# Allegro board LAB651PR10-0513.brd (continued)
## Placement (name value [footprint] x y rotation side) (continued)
J13  -  [JUMP_43X118]  91.79 68.38 180 top
J14  -  [JUMP_43X118]  91.79 61.4 180 top
J15  -  [JUMP_43X118]  133.62 6.15 0 top
J16  -  [JUMP_43X118]  99.41 30.03 180 top
J519  -  [JUMP_43X39]  10.39 66.98 0 top
JDIMM1  -  [BELLW_80001-1021_204P]  96.15 47.7 180 bottom
JEDP  STARC_107K40-000001-G2  [STARC_107K40-000001-G2_40P]  1.76 99 270 bottom
JFAN  ACES_88231-03041  [ACES_88231-03041_3P]  7.05 72.04 180 bottom
JHDD  E&T_4260K-F10N-00L  [E-T_4260K-F10N-00L_10P]  180.71 12.52 180 bottom
JHDMI  CONCR_099ATAC19NBLCNF  [CONCR_099ATAC19NBLCNF_19P]  203.55 89.7 270 bottom
JHDT1  SAMTE_ASP-136446-07-B  [SAMTE_ASP-136446-07-B_20P-T]  92.36 91.1 270 top
JHP  SINGA_2SJ3080-001111F  [SINGA_2SJ3080-001111F_6P]  201.74 36.91 90 bottom
JIO  ACES_51524-0160N-001  [ACES_51524-0160N-001_16P]  25.55 43.95 90 bottom
JKB  HB_A823020-SBHR21  [HB_A823020-SBHR21_30P]  91.75 47.75 270 top
JKBBL  ACES_50524-00401-P01  [ACES_50524-00401-P01_4P-T]  120.35 16.82 270 top
JLAN  J-L_TNBNRAC80015008  [J-L_TNBNRAC80015008_8P]  201.1 109.12 270 bottom
JLED  ACES_51524-0080N-001  [ACES_51524-0080N-001_8P]  12.75 58.3 270 top
JNGFF  LOTES_APCI0019-P009A  [LOTES_APCI0019-P009A_67P]  172.48 57.83 0 bottom
JP3  2MM  [JUMP_43X39]  166.05 115.8 90 bottom
JP13  -  [JUMP_43X79]  188.4 12.16 270 top
JRTC  ACES_50271-0020N-001  [ACES_50271-0020N-001_2P]  28.21 11.33 270 bottom
JSPK  ACES_50278-00401-001  [ACES_50278-00401-001_4P]  208.6 14.05 180 bottom
JTP  ACES_51524-0080N-001  [ACES_51524-0080N-001_8P]  20.65 60.25 0 top
JUSB1  TAITW_PUBAU6-09FLBS1NN4H0  [TAITW_PUBAU6-09FLBS1NN4H0_9P]  199.29 61.75 270 bottom
JUSB2  TAITW_PUBAU6-09FLBS1NN4H0  [TAITW_PUBAU6-09FLBS1NN4H0_9P]  199.29 43.55 270 bottom
LA1  BLM15BB221SN1D_2P  [MURAT_BLM15BB221SN1D_2P]  199.07 14.53 270 bottom
LA3  BLM15BB121SN1D_0402  [R_0402]  210.45 16.92 90 top
LA4  BLM15BB121SN1D_0402  [R_0402]  208.21 16.91 90 top
LA5  BLM15BB121SN1D_0402  [R_0402]  205.61 16.9 90 top
LA6  BLM15BB121SN1D_0402  [R_0402]  203.43 16.9 90 top
LA7  BLM15PX330SN1D 0402  [MURAT_BLM15BD601SN1D_2P]  191.57 33.2 180 bottom
LA8  CHILISIN NBQ100505T-800Y-N_0402  [MURAT_BLM15BD601SN1D_2P]  191.48 29.07 180 bottom
LA9  CHILISIN NBQ100505T-800Y-N_0402  [MURAT_BLM15BD601SN1D_2P]  191.48 27.49 180 bottom
LA10  BLM15PX330SN1D 0402  [MURAT_BLM15BD601SN1D_2P]  191.57 31.42 180 bottom
LE1  FBMA-L11-160808-800LMT_0603  [KC_FBMA-L11-160808-800LMT_2P]  108.13 35.48 270 bottom
LE2  FBMA-L11-160808-800LMT_0603  [KC_FBMA-L11-160808-800LMT_2P]  109.66 35.48 270 bottom
LH1  HCB1608KF-221T20_0603  [CHENG_MBK1608221YZF_2P]  167.99 8.82 180 top
LH5  FBMA-L11-201209-221LMA30T_0805  [R_0805]  151.57 4.41 90 top
LH6  HCB1608KF-221T20_0603  [CHENG_MBK1608221YZF_2P]  159.95 6.62 90 top
LH7  HCB1608KF-221T20_0603  [CHENG_MBK1608221YZF_2P]  166.39 10.09 0 top
LH9  HCB1608KF-221T20_0603  [CHENG_MBK1608221YZF_2P]  153.77 2.49 90 top
LH10  HCB1608KF-221T20_0603  [CHENG_MBK1608221YZF_2P]  149.83 6.02 180 top
LH11  HCB1608KF-221T20_0603  [CHENG_MBK1608221YZF_2P]  155.11 2.49 90 top
LH12  HCB1608KF-221T20_0603  [CHENG_MBK1608221YZF_2P]  166.93 4.08 270 top
LH13  HCB1608KF-221T20_0603  [CHENG_MBK1608221YZF_2P]  171.78 30.47 180 top
LH14  HCB1608KF-221T20_0603  [CHENG_MBK1608221YZF_2P]  171.78 29.14 180 top
LH15  FBMA-L11-201209-221LMA30T_0805  [R_0805]  156.65 4.08 270 top
LI1  DLW21HN670HQ2L_4P  [MURAT_DLW21SN670HQ2L_4P]  196.93 68.6 270 bottom
LI2  MURATA DLW21SN900HQ2L  [KC_WCM-2012HS-900T_4P]  195.02 59.53 90 bottom
LI3  DLW21HN670HQ2L_4P  [MURAT_DLW21SN670HQ2L_4P]  195.15 68.6 270 bottom
LI4  DLW21HN670HQ2L_4P  [MURAT_DLW21SN670HQ2L_4P]  188.31 48.08 0 bottom
LI5  MURATA DLW21SN900HQ2L  [KC_WCM-2012HS-900T_4P]  188.31 43.22 0 bottom
LI6  DLW21HN670HQ2L_4P  [MURAT_DLW21SN670HQ2L_4P]  188.31 46.3 0 bottom
LI7  MURATA DLW21SN900HQ2L  [KC_WCM-2012HS-900T_4P]  30.75 57.86 180 bottom
LI8  MURATA DLW21SN900HQ2L  [KC_WCM-2012HS-900T_4P]  30.75 54.87 180 bottom
LL1  2.2UH_LQM2MPN2R2NG0L_30%  [MURAT_LQM2MPN2R2NG0L_2P]  167.35 109.4 180 bottom
LV2  BLM15BD121SN1D_0402  [R_0402]  80.14 84.76 180 bottom
LV3  BLM15BD121SN1D_0402  [R_0402]  74.81 76.13 180 top
LV4  BLM15BD121SN1D_0402  [R_0402]  68.64 86.42 270 top
LV6  BLM15BB221SN1D_2P  [MURAT_BLM15BB221SN1D_2P]  60.13 99.74 270 top
LV7  BLM15BD121SN1D_0402  [R_0402]  55.81 93.27 0 top
LV8  BLM15BD121SN1D_0402  [R_0402]  57.84 96.02 270 top
LV25  BLM15BD121SN1D_0402  [R_0402]  60.64 82.17 0 top
LV26  BLM15BD121SN1D_0402  [R_0402]  60.64 81.31 0 top
LX1  FBMA-L11-201209-221LMA30T_0805  [KC_FBMA-L11-201209-221LMA30_2P]  12.38 84.96 90 top
LX2  MURATA DLW21HN900HQ2L  [KC_WCM-2012HS-900T_4P]  196.69 82.33 0 bottom
LX3  MURATA DLW21HN900HQ2L  [KC_WCM-2012HS-900T_4P]  196.69 78.78 0 bottom
LX4  MURATA DLW21HN900HQ2L  [KC_WCM-2012HS-900T_4P]  196.69 85.89 0 bottom
LX5  MURATA DLW21HN900HQ2L  [KC_WCM-2012HS-900T_4P]  196.69 89.44 0 bottom
LX6  MURATA DLW21SN900HQ2L  [KC_WCM-2012HS-900T_4P]  5.64 85.46 180 top
NOREF  -  []  165.8 69.8 0 top
NOREF#2  -  []  115.1 82 0 top
NOREF#3  -  []  183 32.1 0 top
NOREF#4  -  []  181.73 91.35 0 top
NOREF#5  -  []  41.67 60.57 0 top
NOREF#6  -  []  102.67 41.83 0 top
NOREF#7  -  []  22.1 92.1 0 top
NOREF#8  -  []  195 4 0 top
NOREF#9  -  []  195.5 96.4 0 top
NOREF#10  -  []  21.8 9.8 0 top
NOREF#11  -  []  115.1 107.4 0 top
NOREF#12  -  []  72.29 -30.86 0 top
NOREF#13  -  []  82.8 57.8 0 top
NOREF#14  -  []  105.85 50.6 0 top
NOREF#15  -  []  27.8 118.8 0 top
NOREF#16  -  []  68.32 163 0 top
NOREF#17  -  []  117.6 65.21 0 top
NOREF#18  -  []  160.1 107.4 0 top
NOREF#19  -  []  86.32 106.83 0 top
NOREF#20  -  []  101 3.5 0 top
NOREF#21  -  []  166.72 76.62 0 top
NOREF#22  -  []  160.1 82 0 top
NOREF#23  -  []  137.6 44.95 0 top
NOREF#24  -  []  102.42 76.45 180 bottom
NOREF#25  -  []  106.74 79.58 180 bottom
NOREF#26  -  []  113.66 95.08 180 bottom
NOREF#27  -  []  151.6 64.55 180 bottom
PBATT  LLTOP_ALLTOP C144LS-109A9-L 9P BATT P2  [ALLTO_C144LS-109A9-L_9P-T]  13.95 12.52 90 bottom
PC1  1000P_0402_50V7K  [C_0402]  16.44 116.84 270 bottom
PC2  100P_0402_50V8J  [C_0402]  17.33 116.84 270 bottom
PC3  1000P_0402_50V7K  [C_0402]  17.33 113.77 90 bottom
PC4  100P_0402_50V8J  [C_0402]  16.31 113.77 90 bottom
PC5  0.1U_0402_25V6  [C_0402]  36.56 108.13 0 top
PC7  0.01U_0402_25V7K  [C_0402]  24.95 28.17 90 top
PC8  1000P_0402_50V7K  [C_0402]  19.23 30.46 90 top
PC9  10P_0402_25V8J  [C_0402]  25.84 28.17 90 top
PC13  0.1U_0402_16V7K  [C_0402]  127.08 28.25 180 bottom
PC16  0.1U_0402_16V7K  [C_0402]  36.51 113.67 270 top
PC100  4.7U_0603_6.3V6K  [C_0603]  75.22 9.29 180 top
PC101  220U_6.3V_M  [C_MP6VLPS220MC4R2]  70.65 27.86 90 bottom
PC102  100P_0402_50V8J  [C_0402]  76.35 20.11 180 top
PC103  680P_0402_50V7K  [C_0402]  70.34 22.99 270 top
PC104  0.22U_0603_25V7K  [C_0603]  73.21 21.45 90 top
PC105  1U_0603_25V6K  [C_0603]  70.33 18.83 270 bottom
PC106  4.7U_0603_10V6K  [C_0603]  68.23 17.86 270 bottom
PC107  220U_6.3V_M  [C_MP6VLPS220MC4R2]  71 8.36 270 bottom
PC108  100P_0402_50V8J  [C_0402]  75.42 16.82 0 bottom
PC109  4.7U_0603_10V6K  [C_0603]  75.49 18.1 0 top
PC110  0.22U_0603_25V7K  [C_0603]  71.77 12.98 90 top
PC111  680P_0402_50V7K  [C_0402]  67.43 14.01 90 top
PC112  10U_0805_25V6K  [C_0805]  62.81 19.49 0 bottom
PC113  0.1U_0402_25V6  [C_0402]  62.85 18.44 0 top
PC114  2200P_0402_50V7K  [C_0402]  62.85 19.33 0 top
PC115  10U_0805_25V6K  [C_0805]  62.32 20.63 0 top
PC118  10P_0402_25V8J  [C_0402]  62.87 18.17 0 bottom
PC119  10P_0402_25V8J  [C_0402]  62.87 17.28 0 bottom
PC200  0.1U_0603_25V7K  [C_0603]  88.89 13.01 180 bottom
PC201  2200P_0402_50V7K  [C_0402]  83.11 16.49 90 bottom
PC202  0.1U_0402_10V7K  [C_0402]  81.03 10.6 180 bottom
PC203  0.1U_0402_10V7K  [C_0402]  81.03 8.82 180 bottom
PC204  1U_0603_10V6K  [C_0603]  84.13 15.99 270 top
PC205  10U_0805_6.3V6K  [C_0805]  88.7 9.42 270 bottom
PC206  10U_0805_25V6K  [C_0805]  86.29 16.22 90 bottom
PC207  680P_0402_50V7K  [C_0402]  89.29 21.77 180 bottom
PC208  0.1U_0402_25V6  [C_0402]  82.23 16.49 90 bottom
PC209  1U_0603_10V6K  [C_0603]  82.86 14.6 90 top
PC210  0.033U_0402_16V7K  [C_0402]  84.13 8.26 270 bottom
PC211  10U_0805_6.3V6K  [C_0805]  87.27 7.93 180 bottom
PC212  10U_0805_25V6K  [C_0805]  84.51 16.22 90 bottom
PC213  330U_2.5V_M  [C_MP6VU330MC6]  99.37 10.98 180 bottom
PC214  220P_0402_25V8J  [C_0402]  81.9 7.8 0 top
PC215  10P_0402_25V8J  [C_0402]  81.34 16.49 90 bottom
PC300  330U_D2_2V_Y  [C_D2]  172.52 41.25 90 bottom
PC301  0.1U_0402_25V6  [C_0402]  176.97 49.13 90 top
PC302  2200P_0402_50V7K  [C_0402]  176.08 49.13 90 top
PC303  10U_0805_25V6K  [C_0805]  178.02 48.57 0 top
PC304  10U_0805_25V6K  [C_0805]  178.02 46.79 0 top
PC305  0.1U_0603_25V7K  [C_0603]  177.92 48.82 0 bottom
PC306  0.1U_0402_16V7K  [C_0402]  179.89 54.74 270 top
PC307  1U_0603_6.3V6M  [C_0603]  180.46 49.46 0 bottom
PC309  680P_0402_50V7K  [C_0402]  184.54 46.73 180 top
PC310  22U_0603_6.3V6M  [C_0603]  206.74 6.76 0 top
PC311  68P_0402_50V8J  [C_0402]  210.48 10.98 180 top
PC312  22U_0603_6.3V6M  [C_0603]  203.23 10.67 0 top
PC313  22U_0603_6.3V6M  [C_0603]  203.23 11.98 0 top
PC314  0.1U_0402_16V7K  [C_0402]  205.64 11.28 90 top
PC315  680P_0402_50V7K  [C_0402]  206.74 4.74 90 top
PC316  10P_0402_25V8J  [C_0402]  174.11 45.34 270 top
PC400  22U_0603_6.3V6M  [C_0603]  110.48 7.93 0 bottom
PC401  22U_0603_6.3V6M  [C_0603]  110.48 9.2 0 bottom
PC402  68P_0402_50V8J  [C_0402]  110.42 2.26 90 bottom
PC403  22U_0603_6.3V6M  [C_0603]  121.09 4.18 270 bottom
PC404  1U_0402_10V6K  [C_0402]  109.15 5.31 90 bottom
PC405  22U_0603_6.3V6M  [C_0603]  121.09 5.58 90 bottom
PC406  22U_0603_6.3V6M  [C_0603]  122.36 5.58 90 bottom
PC407  22U_0603_6.3V6M  [C_0603]  122.36 4.18 270 bottom
PC408  0.1U_0402_16V7K  [C_0402]  113.21 3.18 270 bottom
PC409  680P_0402_50V7K  [C_0402]  113.98 9.78 270 bottom
PC410  0.1U_0402_16V7K  [C_0402]  110.4 4.28 180 bottom
PC411  22U_0603_6.3V6M  [C_0603]  86.57 25.25 180 bottom
PC412  68P_0402_50V8J  [C_0402]  82.9 29.52 0 bottom
PC413  22U_0603_6.3V6M  [C_0603]  92.45 28 0 bottom
PC414  22U_0603_6.3V6M  [C_0603]  90.8 28 180 bottom
PC415  0.1U_0402_16V7K  [C_0402]  87.74 29.82 90 bottom
PC416  680P_0402_50V7K  [C_0402]  86.59 23.03 90 bottom
PC500  0.01U_0402_50V7K  [C_0402]  64.12 119.31 0 top
PC501  680P_0402_50V7K  [C_0402]  58.78 120.2 0 top
PC502  0.1U_0603_25V7K  [C_0603]  61.02 117.83 270 bottom
PC503  10U_0805_25V6K  [C_0805]  72.5 105.94 0 top
PC504  10U_0805_25V6K  [C_0805]  72.79 103.43 0 top
PC505  10U_0805_25V6K  [C_0805]  72.36 103.43 0 bottom
PC506  330P_0402_50V  [C_0402]  58.78 119.31 0 top
PC507  0.22U_0603_25V7K  [C_0603]  70.35 111.43 180 top
PC508  0.1U_0402_16V7K  [C_0402]  64.75 107.4 0 bottom
PC509  470P_0402_50V8J  [C_0402]  63.25 118.42 180 top
PC510  68P_0402_50V8J  [C_0402]  61.47 118.42 180 top
PC511  680P_0603_50V7K  [C_0603]  79.62 110.93 180 bottom
PC512  0.1U_0402_25V6  [C_0402]  64.83 108.44 90 bottom
PC513  1U_0402_6.3V6K  [C_0402]  60.84 113.72 180 bottom
PC514  2.2U_0603_10V7K  [C_0603]  60.64 107.5 270 top
PC515  2.2U_0603_10V7K  [C_0603]  68.95 116.51 0 top
PC518  100U_25V_M  [C_ECST250ADA101MF611]  72.62 114.07 270 bottom
PC519  10U_0805_25V6K  [C_0805]  78.8 116.43 90 bottom
PC520  10U_0805_25V6K  [C_0805]  81.5 113.85 0 bottom
PC521  10U_0805_25V6K  [C_0805]  81.5 113.85 0 top
PC522  0.1U_0402_25V6  [C_0402]  81.9 112.45 0 bottom
PC523  2200P_0402_50V7K  [C_0402]  81.9 112.45 0 top
PC524  0.22U_0603_25V7K  [C_0603]  70.35 115.24 180 top
PC525  0.1U_0402_16V7K  [C_0402]  66.81 118.42 180 top
PC526  0.1U_0402_25V6  [C_0402]  56.19 116.44 90 top
PC527  0.1U_0402_25V6  [C_0402]  57.08 115.57 270 top
PC528  680P_0603_50V7K  [C_0603]  87.75 113.72 180 top
PC529  68P_0402_50V8J  [C_0402]  63.51 107.5 180 top
PC530  470P_0402_50V8J  [C_0402]  65.28 107.5 180 top
PC531  330P_0402_50V  [C_0402]  67.06 107.5 180 top
PC532  0.1U_0402_25V6  [C_0402]  67.67 120.2 0 top
PC533  680P_0402_50V7K  [C_0402]  67.06 105.72 180 top
PC534  0.01U_0402_50V7K  [C_0402]  68.81 106.61 0 top
PC535  0.1U_0402_25V6  [C_0402]  65.72 110.21 90 bottom
PC700  0.1U_0603_25V7K  [C_0603]  31.22 33.83 270 top
PC701  5600P_0402_25V7K  [C_0402]  29.74 30.83 270 top
PC702  4.7U_0805_25V6-K  [C_0805]  37.01 31.12 270 top
PC703  4.7U_0805_25V6-K  [C_0805]  38.77 31.12 270 top
PC704  2200P_0402_25V7K  [C_0402]  34.45 30.61 270 top
PC705  0.1U_0603_25V7K  [C_0603]  35.52 30.99 270 top
PC706  0.1U_0603_25V7K  [C_0603]  47.4 17.4 270 top
PC707  0.1U_0603_25V7K  [C_0603]  46.16 17.4 270 top
PC708  0.1U_0402_10V7K  [C_0402]  25.21 37.87 90 top
PC709  0.047U_0603_25V7M  [C_0603]  47.49 18.98 180 bottom
PC710  1U_0603_10V6K  [C_0603]  44.94 17.4 270 top
PC711  1U_0603_25V6K  [C_0603]  41.18 16.54 0 top
PC712  0.01U_0402_50V7K  [C_0402]  46.35 15.06 0 top
PC713  0.1U_0603_25V7K  [C_0603]  42.68 20.6 270 bottom
PC714  1U_0603_10V6K  [C_0603]  41.18 15.27 0 top
PC715  0.1U_0402_10V7K  [C_0402]  43.95 11.91 90 top
PC716  680P_0402_50V7K  [C_0402]  44.65 30.5 180 bottom
PC717  10U 25V K X5R 0805  [C_0805]  27.11 20.29 270 bottom
PC718  10U 25V K X5R 0805  [C_0805]  25.2 20.29 270 bottom
PC719  10U 25V K X5R 0805  [C_0805]  23.3 20.29 270 bottom
PC720  10U 25V K X5R 0805  [C_0805]  21.39 20.29 270 bottom
PC721  2200P_0402_25V7K  [C_0402]  47.26 13.3 180 top
PC722  0.22U_0603_25V7K  [C_0603]  38.29 15.24 270 top
PC723  0.1U_0402_10V7K  [C_0402]  48.62 11.31 0 bottom
PC725  0.1U_0402_16V7K  [C_0402]  46.97 9.94 270 bottom
PC726  0.1U_0603_25V7K  [C_0603]  38.28 12.78 270 top
PC727  0.01U_0402_25V7K  [C_0402]  50.39 12.21 270 bottom
PC728  1U_0603_25V6K  [C_0603]  30.77 38.11 0 top
PC836  330U_D3_2.5VY_R6M  [C_D3]  67.37 63.71 270 top
PC837  330U_D3_2.5VY_R6M  [C_D3]  67.14 68.13 180 top
PC838  330U_D2_2V_Y  [C_D2]  59.38 63.94 180 bottom
PC839  330U_D2_2V_Y  [C_D2]  63.47 63.95 0 bottom
PC840  2.2U_0402_6.3V6M  [C_0402]  64.98 87.05 270 top
PC841  2.2U_0402_6.3V6M  [C_0402]  61.45 88.35 0 top
PC842  2.2U_0402_6.3V6M  [C_0402]  64.4 89.26 180 top
PC843  2.2U_0402_6.3V6M  [C_0402]  62.74 66.86 180 bottom
PC844  2.2U_0402_6.3V6M  [C_0402]  65.79 67.75 180 bottom
PC845  2.2U_0402_6.3V6M  [C_0402]  65.79 69.52 180 bottom
PC846  2.2U_0402_6.3V6M  [C_0402]  62.74 69.52 180 bottom
PC847  2.2U_0402_6.3V6M  [C_0402]  67.75 67.03 90 bottom
PC848  2.2U_0402_6.3V6M  [C_0402]  66.86 67.03 90 bottom
PC849  2.2U_0402_6.3V6M  [C_0402]  62.74 68.64 180 bottom
PC850  2.2U_0402_6.3V6M  [C_0402]  65.79 68.64 180 bottom
PC851  2.2U_0402_6.3V6M  [C_0402]  67.38 83.21 90 top
PC852  2.2U_0402_6.3V6M  [C_0402]  63.55 82.26 90 top
PC853  10U_0603_6.3V6M  [C_0603]  68.81 66.9 90 bottom
PC854  10U_0603_6.3V6M  [C_0603]  54.46 64.33 180 top
PC855  10U_0603_6.3V6M  [C_0603]  69.16 59.67 90 bottom
PC856  10U_0603_6.3V6M  [C_0603]  70.08 66.9 90 bottom
PC857  10U_0603_6.3V6M  [C_0603]  54.45 65.56 180 top
PC858  10U_0603_6.3V6M  [C_0603]  69.16 58.53 270 bottom
PC859  0.1U_0402_10V7K  [C_0402]  62.74 67.75 180 bottom
PC860  0.1U_0402_10V7K  [C_0402]  65.79 66.86 180 bottom
PC869  2.2U_0402_6.3V6M  [C_0402]  62.74 70.41 180 bottom
PC871  2.2U_0402_6.3V6M  [C_0402]  66.73 88.29 180 top
PC872  2.2U_0402_6.3V6M  [C_0402]  66.86 89.26 90 top
PC901  22U_0603_6.3V6M  [C_0603]  135.58 94.45 270 top
PC902  22U_0603_6.3V6M  [C_0603]  136.85 96.87 270 top
PC903  22U_0603_6.3V6M  [C_0603]  135.58 96.87 270 top
PC904  22U_0603_6.3V6M  [C_0603]  136.85 99.28 270 top
PC905  22U_0603_6.3V6M  [C_0603]  135.58 99.28 270 top
PC906  22U_0603_6.3V6M  [C_0603]  136.85 101.69 270 top
PC907  22U_0603_6.3V6M  [C_0603]  135.58 101.69 270 top
PC908  22U_0603_6.3V6M  [C_0603]  140.02 94.45 270 top
PC909  22U_0603_6.3V6M  [C_0603]  141.29 94.45 270 top
PC910  22U_0603_6.3V6M  [C_0603]  136.85 94.45 270 top
PC911  22U_0603_6.3V6M  [C_0603]  138.75 94.45 270 top
PC912  22U_0603_6.3V6M  [C_0603]  140.02 96.87 270 top
PC913  22U_0603_6.3V6M  [C_0603]  138.75 96.87 270 top
PC914  0.22U_0402_10V6K  [C_0402]  137.1 91.14 90 top
PC915  0.22U_0402_10V6K  [C_0402]  137.99 91.14 90 top
PC916  0.01U_0402_25V7K  [C_0402]  135.32 91.14 90 top
PC917  0.01U_0402_25V7K  [C_0402]  136.21 91.14 90 top
PC918  0.01U_0402_25V7K  [C_0402]  139.77 91.14 90 top
PC919  180P_0402_50V8J  [C_0402]  141.54 91.14 90 top
PC920  180P_0402_50V8J  [C_0402]  140.65 91.16 90 top
PC921  180P_0402_50V8J  [C_0402]  138.88 91.14 90 top
PC922  330U_D2_2V_Y  [C_D2]  102.42 119.21 270 bottom
PC923  330U_D3_2.5VY_R6M  [C_D3]  131.73 114.79 180 top
PC924  330U_D3_2.5VY_R6M  [C_D3]  150.15 114.25 0 top
PC931  22U_0603_6.3V6M  [C_0603]  130.88 94.45 270 top
PC932  22U_0603_6.3V6M  [C_0603]  133.67 94.45 270 top
PC933  22U_0603_6.3V6M  [C_0603]  132.27 94.45 270 top
PC934  22U_0603_6.3V6M  [C_0603]  132.27 96.87 270 top
PC935  22U_0603_6.3V6M  [C_0603]  130.88 96.87 270 top
PC936  22U_0603_6.3V6M  [C_0603]  130.88 101.69 270 top
PC937  22U_0603_6.3V6M  [C_0603]  132.27 101.69 270 top
PC938  22U_0603_6.3V6M  [C_0603]  133.67 101.69 270 top
PC939  22U_0603_6.3V6M  [C_0603]  132.27 99.28 270 top
PC940  22U_0603_6.3V6M  [C_0603]  133.67 99.28 270 top
PC941  22U_0603_6.3V6M  [C_0603]  130.88 99.28 270 top
PC942  22U_0603_6.3V6M  [C_0603]  133.67 96.87 270 top
PC943  0.22U_0402_10V6K  [C_0402]  134.05 91.13 90 top
PC944  0.22U_0402_10V6K  [C_0402]  130.75 89.39 270 top
PC945  0.22U_0402_10V6K  [C_0402]  131.64 89.39 270 top
PC946  180P_0402_50V8J  [C_0402]  131.64 91.14 90 top
PC947  180P_0402_50V8J  [C_0402]  133.16 89.39 270 top
PC948  180P_0402_50V8J  [C_0402]  130.75 91.14 90 top
PC949  180P_0402_50V8J  [C_0402]  133.16 91.14 90 top
PC950  330U_D3_2.5VY_R6M  [C_D3]  111.79 114.91 0 top
PC951  330U_D3_2.5VY_R6M  [C_D3]  107.24 111.66 90 top
PC952  330U_D2_2V_Y  [C_D2]  107.54 110.21 270 bottom
PC1019  0.1U_0402_25V6K  [C_0402]  60.01 32.58 90 top
PC1020  1U_0603_10V6K  [C_0603]  61.21 39.17 180 top
PC1021  1U_0603_10V6K  [C_0603]  63.3 40.38 90 top
PC1022  1000P_0402_50V7K  [C_0402]  58.12 33.43 270 top
PC1023  10U_0805_25V6K  [C_0805]  57.84 45.22 90 top
PC1024  10U_0805_25V6K  [C_0805]  57.84 45.22 90 bottom
PC1025  2200P_0402_50V7K  [C_0402]  59.24 45.65 90 top
PC1026  0.22U_0603_25V7K  [C_0603]  59.49 43.17 270 bottom
PC1027  1000P_0402_50V7K  [C_0402]  57.16 39.55 180 top
PC1028  180P_0402_50V8J  [C_0402]  57.16 38.92 180 bottom
PC1029  680P_0603_50V7K  [C_0603]  56.24 46.22 90 bottom
PC1030  330P_0402_50V7K  [C_0402]  57.16 36.89 180 top
PC1031  0.01U_0402_50V7K  [C_0402]  57.16 35.87 180 bottom
PC1032  0.22U_0603_16V7K  [C_0603]  55.17 35.81 270 bottom
PC1033  390P_0402_50V7K  [C_0402]  54.08 39.43 0 bottom
PC1034  330P_0402_50V  [C_0402]  52.3 39.43 0 bottom
PC1035  0.1U_0603_50V7K  [C_0603]  56.38 35.12 0 top
PC1036  820P_0402_50V7K  [C_0402]  56.24 36.89 0 bottom
PC1040  0.01U_0402_50V7K  [C_0402]  58.02 38.66 0 top
PC1041  10U_0805_25V6K  [C_0805]  60.64 45.22 90 top
PC1042  0.1U_0402_25V6  [C_0402]  59.24 45.65 90 bottom
PC1043  0.22U_0603_25V7K  [C_0603]  63.56 43.3 270 bottom
PC1044  680P_0603_50V7K  [C_0603]  74.34 48.34 270 top
PC1045  2200P_0402_50V7K  [C_0402]  62.03 45.65 90 bottom
PC1046  10U_0805_25V6K  [C_0805]  63.43 45.25 90 bottom
PC1047  0.1U_0402_25V6K  [C_0402]  62.03 45.65 90 top
PC1048  10U_0805_25V6K  [C_0805]  63.43 45.25 90 top
PC1049  10U_0805_25V6K  [C_0805]  60.64 45.22 90 bottom
PC1050  0.22U_0402_10V6K  [C_0402]  56.24 33.68 0 bottom
PC1051  0.22U_0402_10V6K  [C_0402]  56.24 34.98 0 bottom
PC1052  10U 25V K X5R 0805  [C_0805]  65.33 45.25 90 bottom
PC1100  0.1U_0402_25V6  [C_0402]  40.37 41.2 0 top
PC1101  2200P_0402_50V7K  [C_0402]  40.37 40.06 0 top
PC1102  10U_0805_25V6K  [C_0805]  39.97 42.6 0 top
PC1103  0.1U_0603_25V7K  [C_0603]  35.49 44.7 90 bottom
PC1104  0.1U_0402_16V7K  [C_0402]  30.59 41.97 0 bottom
PC1105  1U_0603_10V6K  [C_0603]  35.49 47.24 90 bottom
PC1106  680P_0402_50V7K  [C_0402]  40.24 50.35 0 top
PC1108  330U_2.5V_M  [C_MP6VU330MC6]  43.62 52.63 180 bottom
PC1109  10P_0402_25V8J  [C_0402]  40.37 44.12 0 top
PC1300  22U_0603_6.3V6M  [C_0603]  74.54 65.59 0 bottom
PC1301  22U_0603_6.3V6M  [C_0603]  73.93 51.34 180 bottom
PC1302  0.1U_0402_10V7K  [C_0402]  74.1 52.38 180 top
PC1303  22U_0603_6.3V6M  [C_0603]  74.54 66.78 0 bottom
PC1304  680P_0402_50V7K  [C_0402]  76.38 54.92 180 top
PC1305  22U_0603_6.3V6M  [C_0603]  73.26 66.79 180 bottom
PC1306  22P_0402_50V8J  [C_0402]  77.27 53.27 270 top
PC1307  0.1U_0402_10V7K  [C_0402]  76.38 55.3 270 bottom
PC1308  22U_0603_6.3V6M  [C_0603]  73.26 65.57 180 bottom
PC1309  22U_0603_6.3V6M  [C_0603]  73.93 50.12 180 bottom
PD1  -  [TVNST52302AB0_SOT523-3]  17.77 18.72 90 top
PD2  -  [TVNST52302AB0_SOT523-3]  19.17 22.03 270 top
PD101  -  [TVNST52302AB0_SOT523-3]  74.43 12.92 180 top
PH1  100K_0402_1%_TSM0B104F4251RZ  [R_0402]  126.92 91.66 0 top
PH500  100K_0402_1%_TSM0B104F4251RZ  [R_0402]  98.02 102.42 0 bottom
PH501  100K_0402_1%_TSM0B104F4251RZ  [R_0402]  94.62 112.83 180 bottom
PH1002  470K_0402_5%_TSM0B474J4702RE  [R_0402]  50.56 44.56 270 top
PH1003  10K_0402_5%_ERTJ0ER103J  [R_0402]  50.88 57.52 90 bottom
PJP100  PAD-OPEN 4x4m  [JUMP_43X118]  75.5 20.77 0 bottom
PJP101  PAD-OPEN 4x4m  [JUMP_43X118]  76.09 13.77 0 bottom
PJP102  PAD-OPEN 4x4m  [JUMP_43X118]  75.5 26.04 0 bottom
PJP103  PAD-OPEN 4x4m  [JUMP_43X118]  76.09 8.56 0 bottom
PJP200  -  [JUMP_43X118]  101.4 24.91 90 bottom
PJP201  -  [JUMP_43X118]  96.2 24.91 90 bottom
PJP203  -  [JUMP_43X39]  90.68 7.98 90 bottom
PJP300  -  [JUMP_43X118]  171.55 44.51 180 top
PJP301  -  [JUMP_43X79]  211.22 7.32 180 top
PJP302  -  [JUMP_43X79]  201.52 10.72 180 top
PJP400  -  [JUMP_43X79]  105.81 8.06 0 bottom
PJP401  -  [JUMP_43X118]  124.35 4.75 0 bottom
PJP402  -  [JUMP_43X79]  82.11 25.07 0 bottom
PJP403  -  [JUMP_43X79]  91.62 29.73 90 bottom
PJP1100  -  [JUMP_43X118]  42.47 52.59 90 top
PJP1101  -  [JUMP_43X118]  47.81 52.59 90 top
PJP1300  -  [JUMP_43X79]  73.59 65.97 270 top
PJP1301  -  [JUMP_43X79]  78.37 51.36 0 bottom
PJPDC  ACES_50299-00501-003  [ACES_50299-00501-003_5P]  21.5 112.3 90 top
PL1  FBMJ4516HS720NT_2P  [TAIYO_FBMJ4516HS720NT_2P]  20.38 117.09 270 bottom
PL2  BLM15AG102SN1D_2P  [MURAT_BLM15AG102SN1D_2P]  20.38 105.29 90 top
PL3  FBMJ4516HS720NT_2P  [TAIYO_FBMJ4516HS720NT_2P]  22.48 24.19 180 top
PL4  FBMJ4516HS720NT_2P  [TAIYO_FBMJ4516HS720NT_2P]  26.98 112.65 270 top
PL5  FBMJ4516HS720NT_2P  [TAIYO_FBMJ4516HS720NT_2P]  22.48 26.73 180 top
PL100  2.2UH_7.8A_20%_7X7X3_M  [L_7X7X3_M_2P]  63.35 22.81 90 bottom
PL101  2.2UH_7.8A_20%_7X7X3_M  [L_7X7X3_M_2P]  63.94 14.38 270 bottom
PL102  1UH_6.6A_20%_5X5X3_M  [L_5X5X3_M_2P]  55.92 18.72 0 bottom
PL200  1UH_11A_20%_7X7X3_M  [L_7X7X3_M_2P]  99.48 18.47 180 bottom
PL201  FBMJ4516HS720NT_2P  [TAIYO_FBMJ4516HS720NT_2P]  79.74 20.7 270 bottom
PL300  1UH_6.6A_20%_5X5X3_M  [L_5X5X3_M_2P]  178.49 46.05 270 bottom
PL301  HCB2012KF-121T50_0805  [TAI-T_HCB2012KF-121T50_2P]  174.92 49.59 180 top
PL302  1UH +-20% 2.3A 2.5X2X1.2  [TOKO_1239AS-H-1R0M-P2_2P]  204.38 6.15 180 top
PL400  0.47UH_PCMC042T-R47MN_6A_20%  [CYNTE_PCMC042T-R47MN_2P]  118.04 7.11 270 bottom
PL401  1UH +-20% 2.3A 2.5X2X1.2  [TOKO_1239AS-H-1R0M-P2_2P]  89.1 25.96 0 bottom
PL500  0.36UH_PDME064T-R36MS_24A_20%  [PANAS_ETQP4LR15AFM_4P]  101.19 106.81 180 bottom
PL501  0.36UH_PDME064T-R36MS_24A_20%  [PANAS_ETQP4LR15AFM_4P]  97.94 117.05 180 bottom
PL502  FBMA-L11-453215-800LMA90T_1812  [L_1812-1806]  67.85 117.91 180 bottom
PL700  10UH_PCMB104T-100MS_6A_20%  [CYNTE_PCMB104T-100MS_2P]  40.51 26.89 180 bottom
PL701  1UH_2.8A_30%_4X4X2_F  [L_4X4X2_F_2P]  42.73 37.14 270 bottom
PL1000  FBMJ4516HS720NT_2P  [TAIYO_FBMJ4516HS720NT_2P]  73.08 43.81 270 top
PL1002  0.36UH_PDME064T-R36MS_24A_20%  [PANAS_ETQP4LR15AFM_4P]  55.68 51.13 90 bottom
PL1003  0.36UH_PDME064T-R36MS_24A_20%  [PANAS_ETQP4LR15AFM_4P]  64.32 51.13 90 bottom
PL1100  FBMJ4516HS720NT_2P  [TAIYO_FBMJ4516HS720NT_2P]  38.1 40.19 180 top
PL1101  1UH_11A_20%_7X7X3_M  [L_7X7X3_M_2P]  38.23 45.42 0 bottom
PL1300  0.47UH_PCMC042T-R47MN_6A_20%  [CYNTE_PCMC042T-R47MN_2P]  73.62 59.8 90 bottom
PQ1  L2N7002DW1T1G_SC88-6  [2N7002DW-T-R7_SOT363-6]  34.32 107.36 90 top
PQ2  L2N7002DW1T1G_SC88-6  [2N7002DW-T-R7_SOT363-6]  34.32 112.31 90 top
PQ5  MMST3904-7-F_SOT323  [RHU002N06_SOT323-3]  22.41 101.31 180 top
PQ6  FDV301N_G 1N SOT23-3  [FDV301N_NL_SOT23-3]  22.87 106.71 180 top
PQ101  MDV1528URH-1N-PDFN33-8  [SIS412DN-T1-GE3_POWERPAK8-5]  61.86 25.04 180 top
PQ102  FDMC7692S-1N-MLP  [SIS412DN-T1-GE3_POWERPAK8-5]  64.2 22.17 0 top
PQ103  MDV1528URH-1N-PDFN33-8  [SIS412DN-T1-GE3_POWERPAK8-5]  59.71 13.59 0 top
PQ104  FDMC7692S-1N-MLP  [SIS412DN-T1-GE3_POWERPAK8-5]  65.48 16.46 180 top
PQ200  MDV1528URH-1N-PDFN33-8  [SIS412DN-T1-GE3_POWERPAK8-5]  90.77 16.51 270 bottom
PQ201  FDMC7692S-1N-MLP  [SIS412DN-T1-GE3_POWERPAK8-5]  87.9 18.24 90 bottom
PQ301  MDV1528URH-1N-PDFN33-8  [SIS412DN-T1-GE3_POWERPAK8-5]  175.44 42.31 0 top
PQ303  FDMC7692S-1N-MLP  [SIS412DN-T1-GE3_POWERPAK8-5]  182.02 45.18 180 top
PQ500  CSD87351Q5D_SON8  [CSD86350Q5D_SON8]  73.77 106.08 90 bottom
PQ501  CSD87351Q5D_SON8  [CSD86350Q5D_SON8]  81.41 116.41 90 bottom
PQ701  -  [MDU1516URH_POWERDFN56-8-5]  40.93 28.83 0 top
PQ703  MDU1511RH 1N POWERDFN56-8  [SIR472DP-T1-GE3_POWERPAK8-5]  35.95 26.98 270 top
PQ704  -  [AO4407AL_SO8]  25.63 36.28 270 bottom
PQ705  SI4483ADY_SO8  [SI4459ADY-T1-GE3_SO8]  27.91 33.73 90 bottom
PQ706  -  [AO4407AL_SO8]  21.12 29.46 0 bottom
PQ707  PDTA144EU PNP_SOT323  [DTA144EUA_SC70-3]  27.8 31.88 180 top
PQ708  DDTC115EUA-7-F_SOT323  [DTC115EUA_SC70-3]  25.62 31.81 90 top
PQ709  L2N7002DW1T1G_SC88-6  [2N7002DW-T-R7_SOT363-6]  24.53 34.17 0 top
PQ710  L2N7002DW1T1G_SC88-6  [2N7002DW-T-R7_SOT363-6]  26.55 38.68 270 top
PQ711  DDTC115EUA-7-F_SOT323  [DTC115EUA_SC70-3]  52.65 14.02 90 top
PQ712  DDTC115EUA-7-F_SOT323  [DTC115EUA_SC70-3]  27.8 34.4 0 top
PQ713  L2N7002DW1T1G 2N SC88-6  [2N7002DW-T-R7_SOT363-6]  22.55 34.06 180 top
PQ714  -  [SSM3K7002FU_SC70-3]  31.86 36.23 90 top
PQ1003  -  [MDU1516URH_POWERDFN56-8-5]  55.9 47.45 180 top
PQ1004  MDU1511RH 1N POWERDFN56-8  [SIR472DP-T1-GE3_POWERPAK8-5]  57.87 49.14 90 top
PQ1005  -  [MDU1516URH_POWERDFN56-8-5]  69.14 48.83 180 top
PQ1006  MDU1511RH 1N POWERDFN56-8  [SIR472DP-T1-GE3_POWERPAK8-5]  63.3 54.41 270 top
PQ1100  MDV1528URH-1N-PDFN33-8  [SIS412DN-T1-GE3_POWERPAK8-5]  38.51 45.41 180 top
PQ1101  FDMC7692S-1N-MLP  [SIS412DN-T1-GE3_POWERPAK8-5]  40.23 46.87 90 top
PR1  200K_0402_1%  [R_0402]  37.47 110.04 180 top
PR3  2.2K_0402_5%  [R_0402]  25.33 101.1 270 top
PR4  33_0402_5%  [R_0402]  25.33 104.09 270 top
PR5  3.3K_1206_5%  [R_1206]  30.22 110.55 0 top
PR6  100K_0402_1%  [R_0402]  20.58 101.27 180 top
PR7  1M_0402_1%  [R_0402]  31.12 108.64 180 top
PR8  10K_0402_1%  [R_0402]  24.31 100.18 90 top
PR9  15K_0402_1%  [R_0402]  19.67 100 0 top
PR10  1M_0402_1%  [R_0402]  30.21 107.37 0 top
PR11  0_0402_5%  [R_0402]  25.33 106 270 top
PR15  100_0402_5%  [R_0402]  20.55 19.23 0 top
PR16  10K_0402_1%  [R_0402]  21.47 18.34 180 top
PR18  100_0402_5%  [R_0402]  20.55 21.52 0 top
PR20  100_0402_5%  [R_0402]  20.55 22.53 0 top
PR23  150K_0402_1%  [R_0402]  125.25 30.03 0 bottom
PR24  10.2K_0402_1%  [R_0402]  129.37 26.45 180 bottom
PR25  12.1K_0402_1%  [R_0402]  129.37 25.53 180 bottom
PR26  499K_0402_1%  [R_0402]  127.08 29.14 180 bottom
PR28  10K_0402_1%  [R_0402]  37.39 112.75 90 top
PR29  100K_0402_1%  [R_0402]  36.56 111.82 0 top
PR31  1M_0402_1%  [R_0402]  31.12 112.45 180 top
PR33  1M_0402_1%  [R_0402]  30.21 113.47 0 top
PR100  0_0402_5%  [R0402_0OHM]  75.62 11.31 270 top
PR101  0_0402_5%  [R0402_0OHM]  73.59 11.31 270 top
PR102  2.2K_0402_5%  [R_0402]  74.61 11.31 270 top
PR103  2.2_0603_5%  [R_0603]  71.43 22.85 270 top
PR104  15K_0402_1%  [R_0402]  75.43 17 0 top
PR105  32.4K_0402_1%  [R_0402]  75.42 16.06 0 top
PR106  10K_0402_1%  [R_0402]  75.42 17.71 0 bottom
PR107  20K_0402_1%  [R_0402]  76.35 21 180 top
PR108  26.1K_0402_1%  [R_0402]  75.43 21.89 0 top
PR109  13K_0402_1%  [R_0402]  76.35 19.22 180 top
PR110  20K_0402_1%  [R_0402]  72.57 10.39 90 top
PR111  2.2_0603_5%  [R_0603]  70.52 14.38 270 top
PR112  4.7_1206_5%  [R_1206]  64.62 11.79 0 top
PR113  4.7_1206_5%  [R_1206]  67.68 24.44 0 top
PR114  200_0402_5%  [R_0402]  72.9 14.41 270 top
PR115  100K_0402_5%  [R_0402]  74.35 22.36 270 top
PR200  2.2_0603_5%  [R_0603]  88.96 11.93 270 bottom
PR201  0_0402_5%  [R0402_0OHM]  80.12 9.71 0 bottom
PR202  0_0402_5%  [R0402_0OHM]  80.12 7.93 0 bottom
PR203  4.7_1206_5%  [R_1206]  86.1 20.76 180 bottom
PR204  68.1K_0402_1%  [R_0402]  81.9 7.42 0 bottom
PR205  7.15K_0402_1%  [R_0402]  82.91 14.53 0 bottom
PR206  5.1_0603_5%  [R_0603]  80.83 12.56 90 bottom
PR207  54.9K_0402_1%  [R_0402]  81.9 8.31 0 bottom
PR208  680K_0402_1%  [R_0402]  80.12 11.49 0 bottom
PR209  0_0402_5%  [R0402_0OHM]  89.59 12.86 180 top
PR210  5.1_0603_5%  [R_0603]  80.74 12.35 180 top
PR301  34K_0402_1%  [R_0402]  177.91 55.55 0 bottom
PR302  2.2_0603_5%  [R_0603]  176.77 50.86 270 bottom
PR303  0_0402_5%  [R0402_0OHM]  179 53.83 90 top
PR304  470K_0402_1%  [R_0402]  182.3 54.49 270 bottom
PR305  4.7_1206_5%  [R_1206]  184.1 42.85 90 top
PR306  4.99K_0402_1%  [R_0402]  182.35 55.55 0 bottom
PR307  10K_0402_1%  [R_0402]  180.57 55.55 0 bottom
PR309  15K_0402_1%  [R_0402]  210.52 11.88 180 top
PR310  4.7_0603_5%  [R_0603]  205.61 6.89 270 top
PR311  0_0402_5%  [R0402_0OHM]  207.55 12.2 270 top
PR312  1M_0402_1%  [R_0402]  206.6 11.28 90 top
PR313  10K_0402_1%  [R_0402]  209.57 10.02 0 top
PR401  10_0402_1%  [R_0402]  110.17 6.23 270 bottom
PR402  4.7_0603_5%  [R_0603]  115.25 8.37 90 bottom
PR403  10K_0402_1%  [R_0402]  109.4 2.26 90 bottom
PR404  0_0402_5%  [R0402_0OHM]  114.23 2.26 90 bottom
PR405  12K_0402_1%  [R_0402]  111.44 3.18 270 bottom
PR406  4.7_0603_5%  [R_0603]  87.8 25.33 270 bottom
PR407  20K_0402_1%  [R_0402]  82.9 30.47 0 bottom
PR408  0_0402_5%  [R0402_0OHM]  85.83 30.74 270 bottom
PR409  1M_0402_1%  [R_0402]  86.79 29.82 90 bottom
PR410  10K_0402_1%  [R_0402]  83.81 28.57 180 bottom
PR500  10_0402_5%  [R_0402]  61.47 115.5 180 bottom
PR502  10_0402_5%  [R_0402]  64.12 118.42 0 top
PR507  0_0603_5%  [R0603_0OHM]  68.95 110.16 0 top
PR508  2K_0402_1%  [R_0402]  60.56 120.2 0 top
PR510  2.2_0603_1%  [R_0603]  68.95 108.89 0 top
PR511  10K_0402_1%  [R_0402]  63.25 119.31 180 top
PR513  105K_0402_1%  [R_0402]  61.47 119.31 180 top
PR514  100K_0402_1%  [R_0402]  69.2 118.93 0 top
PR515  2.61K_0402_1%  [R_0402]  66.55 106.53 90 bottom
PR516  4.7_1206_5%  [R_1206]  81.21 108.2 90 bottom
PR518  0_0402_5%  [R_0402]  65.67 106.51 180 bottom
PR519  910_0402_1%  [R_0402]  63.89 107.4 270 bottom
PR520  2.2_0603_5%  [R_0603]  68.95 117.78 0 top
PR521  2.2_0603_5%  [R_0603]  59.43 107.5 270 top
PR526  19.6K_0402_1%  [R_0402]  57.97 116.44 90 top
PR527  6.04K_0402_1%  [R_0402]  58.05 113.72 180 top
PR528  0_0402_5%  [R0402_0OHM]  60.84 111.82 180 bottom
PR529  0_0402_5%  [R0402_0OHM]  60.84 110.93 180 bottom
PR530  100K_0402_1%  [R_0402]  70.59 106.61 0 top
PR531  0_0603_5%  [R0603_0OHM]  68.95 113.97 0 top
PR535  6.8K_0402_1%  [R_0402]  57.07 118.23 0 top
PR536  12K_0402_1%  [R_0402]  55.35 113.72 0 top
PR537  18K_0402_1%  [R_0402]  57.08 116.44 90 top
PR538  12.7K_0402_1%  [R_0402]  57.97 115.57 270 top
PR539  0_0402_5%  [R0402_0OHM]  59.92 110.04 0 bottom
PR540  100K_0402_5%  [R_0402]  61.72 106.6 90 top
PR541  100K_0402_5%  [R_0402]  68.84 107.5 180 top
PR542  2.2_0603_1%  [R_0603]  68.95 112.7 0 top
PR545  2.61K_0402_1%  [R_0402]  66.81 120.2 180 top
PR546  4.7_1206_5%  [R_1206]  91.69 113.72 180 top
PR547  0_0402_5%  [R0402_0OHM]  65.72 108.44 90 bottom
PR549  4.12K_0402_1%  [R_0402]  65.89 119.31 0 top
PR550  105K_0402_1%  [R_0402]  63.51 106.61 180 top
PR552  10K_0402_1%  [R_0402]  65.28 106.61 180 top
PR553  6.2K_0402_5%  [R_0402]  55.35 112.83 0 top
PR554  120_0402_1%  [R_0402]  57.13 112.83 0 top
PR555  20K_0402_5%  [R_0402]  58.05 111.94 180 top
PR557  2K_0402_1%  [R_0402]  65.28 105.72 180 top
PR558  910_0402_1%  [R_0402]  67.68 118.41 90 top
PR559  6.2K_0402_5%  [R_0402]  56.25 109.26 90 top
PR560  120_0402_1%  [R_0402]  57.13 110.16 0 top
PR561  20K_0402_5%  [R_0402]  58.05 111.05 180 top
PR565  10_0402_5%  [R_0402]  68.81 105.72 0 top
PR567  20.5K_0402_1%  [R_0402]  57.13 109.28 0 top
PR569  124K_0402_1%  [R_0402]  58.05 108.39 180 top
PR571  470_0402_1%  [R_0402]  58.35 106.6 90 top
PR573  124K_0402_1%  [R_0402]  57.47 107.5 180 top
PR700  0.01_1206_1%  [R_1206_4P-D]  34.72 37.11 0 bottom
PR701  200K_0402_1%  [R_0402]  30.14 33.35 270 top
PR702  200K_0402_1%  [R_0402]  23.51 36.37 270 top
PR703  150K_0402_1%  [R_0402]  29.25 32.43 90 top
PR704  10_0402_5%  [R_0402]  47.3 20.96 270 bottom
PR705  10_0402_5%  [R_0402]  46.41 20.96 270 bottom
PR706  200K_0402_1%  [R_0402]  51.61 15.84 180 bottom
PR707  10_1206_1%  [R_1206]  37.19 17.21 0 top
PR708  47K_0402_1%  [R_0402]  53.38 15.91 180 top
PR709  4.7_0603_5%  [R_0603]  41.13 19.17 90 bottom
PR710  100K_0402_1%  [R_0402]  41.88 9.03 90 bottom
PR711  232K_0402_1%  [R_0402]  48.88 16.06 0 bottom
PR712  200K_0402_1%  [R_0402]  28.3 33.11 180 top
PR713  0_0603_5%  [R0603_0OHM]  43.9 20.6 270 bottom
PR714  100K_0402_1%  [R_0402]  50.66 15.92 0 top
PR715  49.9K_0402_1%  [R_0402]  46.36 14.17 0 top
PR716  158K_0402_1%  [R_0402]  42.81 9.94 270 bottom
PR717  0_0402_5%  [R0402_0OHM]  44.25 9.02 90 bottom
PR718  10K +-1% 0402  [R_0402]  29.69 38.82 270 top
PR719  0_0402_5%  [R0402_0OHM]  45.14 9.02 90 bottom
PR720  0.01_1206_1%  [R_1206_4P-D]  27.11 26.43 270 bottom
PR721  4.7_1206_5%  [R_1206]  44.35 26.65 90 bottom
PR722  100_0402_1%  [R_0402]  46.08 9.02 90 bottom
PR723  4.7K_0402_5%  [R_0402]  48.62 12.2 0 bottom
PR724  10_0402_5%  [R_0402]  37.15 14.32 90 top
PR725  221K_0402_1%  [R_0402]  49.52 13.97 180 bottom
PR726  100_0402_5%  [R_0402]  39.43 12.58 270 top
PR727  287K_0402_1%  [R_0402]  49.52 14.88 180 bottom
PR728  28.7K_0402_1%  [R_0402]  49.54 13.08 180 bottom
PR729  63.4K_0402_1%  [R_0402]  50.39 13.97 90 bottom
PR730  3.3K_1206_5%  [R_1206]  19.61 36.69 270 top
PR1020  100K_0402_1%  [R_0402]  62.92 31.47 90 bottom
PR1022  0_0402_5%  [R0402_0OHM]  63.15 32.49 180 top
PR1024  1_0603_5%  [R_0603]  62.22 39.17 0 top
PR1025  0_0402_5%  [R_0402]  63.13 33.84 180 top
PR1027  0_0402_5%  [R0402_0OHM]  60.25 31.47 90 bottom
PR1029  133K_0402_1%  [R_0402]  57.19 33.43 270 top
PR1030  100K_0402_1%  [R_0402]  56.24 40.06 0 bottom
PR1031  27.4K_0402_1%  [R_0402]  56.29 33.42 270 top
PR1032  100K_0402_1%  [R_0402]  65.13 31.47 90 bottom
PR1033  100K_0402_1%  [R_0402]  64.24 31.47 90 bottom
PR1034  2.2_0603_1%  [R_0603]  57.84 41.77 90 bottom
PR1035  10K_0402_1%  [R_0402]  66.81 37.14 180 top
PR1036  4.7_1206_5%  [R_1206]  52.22 47.13 0 bottom
PR1037  301_0402_1%  [R_0402]  55.3 39.63 270 top
PR1038  32.4K_0402_1%  [R_0402]  55 40.31 180 bottom
PR1039  3.65K_0603_1%  [R_0603]  51.94 35.87 180 bottom
PR1040  825_0402_1%  [R_0402]  57.16 38.66 180 top
PR1041  56.2K_0402_1%  [R_0402]  55 38.54 180 bottom
PR1042  2.61K_0402_1%  [R_0402]  53.02 35.31 270 bottom
PR1043  1_0402_1%  [R_0402]  51.7 34.47 180 bottom
PR1044  11K_0402_1%  [R_0402]  53.9 35.31 270 bottom
PR1045  2K_0402_1%  [R_0402]  53.22 38.54 180 bottom
PR1046  590_0402_1%  [R_0402]  56.24 37.77 0 bottom
PR1048  100_0402_1%  [R_0402]  55.05 34.78 90 top
PR1049  0_0402_5%  [R0402_0OHM]  57.16 37.77 180 top
PR1050  0_0402_5%  [R0402_0OHM]  52.63 39.37 270 top
PR1052  13.3K_0402_1%  [R_0402]  57.03 31.47 90 bottom
PR1053  1_0402_1%  [R_0402]  53.85 34.47 180 top
PR1054  4.7_1206_5%  [R_1206]  72.6 49.83 270 top
PR1055  2.2_0603_1%  [R_0603]  65.21 41.9 90 bottom
PR1056  10K_0402_1%  [R_0402]  66.81 38.03 180 top
PR1057  3.65K_0603_1%  [R_0603]  51.94 35.87 180 top
PR1058  10K_0402_1%  [R_0402]  51.7 37.01 180 bottom
PR1059  10K_0402_1%  [R_0402]  51.7 34.47 180 top
PR1060  0_0402_5%  [R0402_0OHM]  50.48 47.98 90 top
PR1061  0_0402_5%  [R0402_0OHM]  60.08 54.54 180 top
PR1062  0_0402_5%  [R0402_0OHM]  63.76 48.42 90 top
PR1063  0_0402_5%  [R0402_0OHM]  62.41 48.44 90 top
PR1064  0_0402_5%  [R0402_0OHM]  58.03 31.68 270 bottom
PR1101  2.2_0603_5%  [R_0603]  34.16 43.49 0 bottom
PR1102  48.7K_0402_1%  [R_0402]  31.5 42.85 180 bottom
PR1103  0_0402_5%  [R0402_0OHM]  31.5 41.08 180 bottom
PR1104  4.7_1206_5%  [R_1206]  36.44 50.86 0 top
PR1105  470K_0402_1%  [R_0402]  31.04 49.08 0 bottom
PR1107  9.09K_0402_1%  [R_0402]  31.04 50.86 0 bottom
PR1108  10K_0402_1%  [R_0402]  31.04 49.97 0 bottom
PR1110  100K_0402_5%  [R_0402]  31.5 43.74 180 bottom
PR1300  0_0402_5%  [R0402_0OHM]  77.15 56.32 180 bottom
PR1301  10K_0402_1%  [R_0402]  75.37 52.38 90 top
PR1302  5.9K_0402_1%  [R_0402]  76.26 53.27 270 top
PR1303  4.7_1206_5%  [R_1206]  75.62 58.86 270 top
PR1304  1M +-1% 0402  [R_0402]  77.27 55.3 270 bottom
PU100  -  [TPS51285BRUKR_QFN20_3X3]  73.76 17.31 90 top
PU200  -  [RT8207MZQW_WQFN20_3X3]  84.8 9.68 180 bottom
PU300  -  [TPS51212DSCR_SON10_3X3]  178.49 54.16 0 bottom
PU301  -  [SY8032ABC_SOT23-6]  205.9 10.02 270 top
PU400  -  [SY8036LDBC_DFN10_3X3]  114.79 6.55 270 bottom
PU401  -  [SY8032ABC_SOT23-6]  87.48 28.57 270 bottom
PU500  RT8880BGQW WQFN 52P_6X6  [NCP6151S52MNR2G_QFN52_6X6]  65.75 116.01 180 top
PU700  ISL88731CHRTZ-T TQFN 28P PWM  [BQ24745RHDR_QFN28_5X5]  46.34 15.83 270 bottom
PU1000  -  [ISL62771HRTZ-T_TQFN40_5X5]  63.32 34.14 180 bottom
PU1100  -  [TPS51212DSCR_SON10_3X3]  30.41 45.39 90 bottom
PU1300  SY8036LDBC_DFN10_3X3  [SY8036DBC_DFN10_3X3]  72.95 55.94 0 bottom
Q3  BSH111 1N_SOT23-3  [2N7002_SOT23-3]  172.17 92.38 90 top
Q9  MESS138-G 1N SOT23-3  [BSH111_SOT23-3]  174.17 84.23 0 top
Q10  MESS138-G 1N SOT23-3  [BSH111_SOT23-3]  178.24 84.23 0 top
Q12  -  [MMBT3904_SOT23-3]  146.11 119.33 180 top
Q20  L2N7002LT1G_SOT23-3  [2N7002K_SOT23-3]  5.49 96.96 270 top
Q52  -  [DMN66D0LDW-7_SOT363-6]  121.96 22.09 0 top
Q78  -  [DMN66D0LDW-7_SOT363-6]  177.62 95.87 180 top
Q2407  -  [MMST3904-7-F_SOT323-3]  90.93 34.98 90 bottom
Q2408  -  [MMST3904-7-F_SOT323-3]  117.97 90.23 270 bottom
Q2507  -  [DMN66D0LDW-7_SOT363-6]  173.78 93.97 0 top
QA5  -  [DMN66D0LDW-7_SOT363-6]  190.67 21.58 0 top
QA6  -  [DMN66D0LDW-7_SOT363-6]  190.37 33.85 270 top
QC1  2N7002K_SOT23-3  [2N7002_SOT23-3]  166.55 91.09 0 top
QE4  2N7002KW 1N SOT323-3  [2N7002BKW_SOT323-3]  129.22 12.47 0 bottom
QE5  AP2606AGY-HF 1N SOT26-6  [SI3456BDV-T1-E3_TSOP6]  123.14 12.06 0 bottom
QE30  L2N7002LT1G_SOT23-3  [2N7002K_SOT23-3]  123.63 29.16 180 top
QH2  -  [DMN66D0LDW-7_SOT363-6]  161.79 3.63 270 top
QH31  DMN66D0LDW-7_SOT363-6  [2N7002DW-T-R7_SOT363-6]  144.48 18.61 270 top
QM1  DII-DMN65D8LW-7  [SSM3K7002FU_SC70-3]  187.13 63.11 180 top
QV1  DMN66D0LDW-7 2N SOT363-6  [2N7002KDWH_SOT363-6]  68.09 101.26 90 bottom
QV7  -  [SSM3K7002FU_SC70-3]  11.68 74.6 270 top
QV8  -  [DMN66D0LDW-7_SOT363-6]  74.42 97.61 270 top
QX2  -  [SI3457CDV-T1-GE3_TSOP6]  6.09 74.4 0 top
QX3  -  [2N7002K_SOT23-3]  191.73 90.35 90 top
QX4  -  [DMN66D0LDW-7_SOT363-6]  197.4 77.33 0 bottom
QX5  -  [MMBT3904_NL_SOT23-3]  192.94 73.59 270 top
QX6  -  [DMN66D0LDW-7_SOT363-6]  9.39 105.23 270 top
QX7  -  [DMN66D0LDW-7_SOT363-6]  12.7 102.43 270 top
QZ13  -  [SSM3K7002FU_SC70-3]  162.05 38.03 270 top
QZ15  -  [SSM3K7002FU_SC70-3]  135.31 34.66 180 top
R1  196_0402_1%  [R_0402]  153.36 94.47 270 bottom
R3  39.2_0402_1%  [R_0402]  136.01 87.02 270 top
R5  1K_0402_1%  [R_0402]  144.51 71.56 0 top
R6  1K_0402_5%  [R_0402]  148.22 74.6 180 top
R8  1K_0402_1%  [R_0402]  145.42 72.57 180 top
R13  150_0402_1%  [R_0402]  127.06 113.01 90 bottom
R14  100K_0402_5%  [R_0402]  126.17 113.01 90 bottom
R15  1K_0402_5%  [R_0402]  116.47 99.88 180 bottom
R16  1K_0402_5%  [R_0402]  114.1 99.7 270 bottom
R17  1K_0402_5%  [R_0402]  116.47 98.86 180 bottom
R18  10K_0402_5%  [R_0402]  176.97 91.67 90 top
R22  510_0402_5%  [R_0402]  153.41 100.99 0 bottom
R23  510_0402_5%  [R_0402]  153.41 100.1 0 bottom
R24  0_0402_5%  [R0402_0OHM]  171.84 89.84 180 top
R25  39.2_0402_1%  [R_0402]  136.33 88.37 90 top
R26  39.2_0402_1%  [R_0402]  136.95 87.02 270 top
R27  10K_0402_5%  [R_0402]  153.14 100.26 0 top
R28  10K_0402_5%  [R_0402]  150.86 100.26 0 top
R29  1K_0402_5%  [R_0402]  166.86 89.34 0 top
R30  300_0402_5%  [R_0402]  114.56 100.89 180 bottom
R31  300_0402_5%  [R_0402]  116.47 100.89 180 bottom
R32  0_0402_5%  [R_0402]  117.36 92.1 180 bottom
R33  0_0402_5%  [R_0402]  153.23 101.15 0 top
R34  196_0402_1%  [R_0402]  153.28 92.48 0 bottom
R35  1K_0402_5%  [R_0402]  115.59 94.14 180 bottom
R36  300_0402_5%  [R_0402]  156.91 97.36 90 bottom
R37  300_0402_5%  [R_0402]  105.42 90.99 180 top
R38  33_0402_5%  [R_0402]  88.12 87.05 0 top
R39  300_0402_5%  [R_0402]  161.09 115.32 270 top
R40  300_0402_5%  [R_0402]  158.55 115.32 270 top
R47  10K_0402_5%  [R_0402]  88.12 84.76 0 top
R48  10K_0402_5%  [R_0402]  88.12 83.49 0 top
R50  10K_0402_5%  [R_0402]  88.12 82.22 0 top
R54  0_0402_5%  [R_0402]  126.45 118.33 180 top
R55  1K_0402_1%  [R_0402]  139.18 37.19 0 top
R56  1K_0402_1%  [R_0402]  140.09 38.2 180 top
R57  1K_0402_1%  [R_0402]  99.24 52.05 90 top
R58  0_0402_5%  [R_0402]  98.23 52.05 90 top
R59  1K_0402_1%  [R_0402]  97.21 52.96 270 top
R65  1K_0402_5%  [R_0402]  116.45 93.25 0 bottom
R120  1K_0402_5%  [R_0402]  116.45 94.14 0 bottom
R121  1K_0402_5%  [R_0402]  99.55 86.03 0 top
R122  1K_0402_5%  [R_0402]  99.55 84.76 0 top
R365  100K_0402_5%  [R_0402]  6.33 100.51 0 top
R384  10K_0402_5%  [R_0402]  9.53 99.5 180 top
R407  0_0402_5%  [R_0402]  7.25 99.5 180 top
R435  0_0402_5%  [R_0402]  98.99 63.35 90 top
R436  0_0402_5%  [R_0402]  98.99 66.3 270 top
R437  1K_0402_5%  [R_0402]  134.37 3.1 180 top
R438  0_0402_5%  [R_0402]  126.85 3.1 0 top
R445  0_0402_5%  [R0402_0OHM]  154.19 98.2 180 bottom
R446  0_0402_5%  [R0402_0OHM]  151.77 99.24 180 top
R537  31.6K_0402_1%  [R_0402]  176.21 89.29 270 top
R538  30K_0402_1%  [R_0402]  175.19 88.37 90 top
R616  100K_0402_1%  [R_0402]  6.33 102.54 0 top
R617  100K_0402_1%  [R_0402]  7.25 101.53 180 top
R620  10K_0402_5%  [R_0402]  143.57 117.99 270 top
R621  0_0402_5%  [R_0402]  150.3 120.27 270 top
R622  1K_0402_5%  [R_0402]  149.28 117.07 90 top
R623  0_0402_5%  [R0402_0OHM]  149.28 120.27 270 top
R782  33_0402_5%  [R_0402]  137.85 15.98 90 bottom
R783  33_0402_5%  [R_0402]  136.84 15.98 90 bottom
R785  10_0402_1%  [R_0402]  135.31 9.53 270 bottom
R787  0_0402_5%  [R_0402]  139.38 8.36 90 bottom
R790  0_0402_5%  [R_0402]  132.77 8.61 90 bottom
R791  0_0402_5%  [R_0402]  132.77 11.82 270 bottom
R793  0_0402_5%  [R_0402]  131.76 11.82 270 bottom
R796  330_0402_5%  [R_0402]  140.26 8.36 90 bottom
R2448  10K_0402_5%  [R_0402]  132.72 32.69 180 top
R2450  0_0402_5%  [R_0402]  131.81 33.71 0 top
RA1  100K_0402_5%  [R_0402]  189.59 19.74 0 top
RA2  100K_0402_5%  [R_0402]  189.59 20.63 0 top
RA3  10K_0402_5%  [R_0402]  191.45 19.66 90 top
RA4  0_0402_1%  [R0402_0OHM]  192.33 19.66 90 top
RA5  470K_0402_5%  [R_0402]  193.22 34.04 270 top
RA6  10K_0402_5%  [R_0402]  193.1 14.61 270 bottom
RA7  10K_0402_5%  [R_0402]  189.16 34.93 270 top
RA8  0_0402_5%  [R_0402]  203.59 21.65 180 bottom
RA9  0_0402_5%  [R_0402]  200.34 23.85 90 bottom
RA10  0_0402_5%  [R_0402]  185.83 21.52 0 bottom
RA11  0_0402_5%  [R_0402]  185.83 22.46 0 bottom
RA12  100K_0402_5%  [R_0402]  195.23 25.47 270 top
RA19  10K_0402_5%  [R_0402]  189.67 14.74 270 top
RA28  0_0402_5%  [R_0402]  188.86 21.52 180 bottom
RA29  0_0603_5%  [R0603_0OHM]  196.53 33.52 90 top
RA30  0_0603_5%  [R0603_0OHM]  187.83 25.71 180 top
RA31  0_0603_5%  [R0603_0OHM]  201.59 24.24 180 top
RA32  0_0603_5%  [R0603_0OHM]  187.75 23.54 225 top
RA34  200K_0402_1%  [R_0402]  193.22 19.21 90 top
RA53  2.2K_0402_5%  [R_0402]  189.87 33.33 180 bottom
RA55  8.2_0402_1%  [R_0402]  196.86 24.74 90 bottom
RA56  8.2_0402_1%  [R_0402]  197.75 24.74 90 bottom
RA79  1K_0402_1%  [R_0402]  190.56 13.82 90 top
RA80  1K_0402_1%  [R_0402]  188.75 28.93 90 top
RA81  10K_0402_5%  [R_0402]  192.33 14.74 270 top
RA82  1K_0402_1%  [R_0402]  188.78 27.16 90 top
RA83  10K_0402_5%  [R_0402]  190.73 30.41 0 bottom
RA84  10K_0402_5%  [R_0402]  190.73 26.09 0 bottom
RA130  22_0402_5%  [R_0402]  194.75 13.69 90 bottom
RA155  100K_0402_5%  [R_0402]  191.14 17.07 180 bottom
RA165  4.7K_0402_5%  [R_0402]  188.78 28.12 90 bottom
RA166  4.7K_0402_5%  [R_0402]  188.58 27.23 0 bottom
RA1109  2.2K_0402_5%  [R_0402]  189.87 30.79 180 bottom
RA1110  0_0603_1%  [R0603_0OHM]  197.99 19.49 0 top
RA1111  0_0603_1%  [R0603_0OHM]  194.78 21.28 90 top
RA1112  0_0402_5%  [R_0402]  196.78 14.1 270 bottom
RA1113  0_0402_5%  [R_0402]  197.8 13.44 90 bottom
RC8  1.8K_0402_5%  [R_0402]  148.72 101.4 180 top
RC9  1.8K_0402_5%  [R_0402]  148.72 102.29 180 top
RC13  10K_0402_5%  [R_0402]  166.6 95.18 0 top
RC78  10K_0402_5%  [R_0402]  22.66 62.21 90 top
RE1  0_0805_5%  [R_0805]  105.85 10.76 90 bottom
RE2  0_0805_5%  [R_0805]  107.63 10.76 90 bottom
RE3  100K_0402_1%  [R_0402]  105.85 33.25 90 bottom
RE4  0_0402_5%  [R0402_0OHM]  129.42 23.55 180 bottom
RE5  0_0402_1%  [R_0402]  104.83 34.17 270 bottom
RE6  33_0402_5%  [R_0402]  117.81 11.66 90 bottom
RE7  0_0402_5%  [R_0402]  112.96 34.17 270 bottom
RE8  47K_0402_5%  [R_0402]  104.02 18.72 180 bottom
RE9  4.7K_0402_5%  [R_0402]  119.06 34.17 270 bottom
RE10  4.7K_0402_5%  [R_0402]  119.94 34.17 270 bottom
RE11  0_0402_5%  [R_0402]  104.02 19.61 180 bottom
RE12  0_0402_5%  [R_0402]  121.72 33.25 90 bottom
RE13  0_0402_5%  [R_0402]  120.83 33.25 90 bottom
RE15  0_0402_5%  [R0402_0OHM]  128.5 24.57 0 bottom
RE16  1K_0402_1%  [R_0402]  114.74 11.66 90 bottom
RE21  10K_0402_5%  [R_0402]  110.17 11.66 90 bottom
RE26  0_0402_5%  [R0402_0OHM]  113.98 34.17 270 bottom
RE27  0_0402_5%  [R0402_0OHM]  114.99 34.17 270 bottom
RE28  0_0402_5%  [R0402_0OHM]  116.01 34.17 270 bottom
RE29  0_0402_5%  [R0402_0OHM]  116.9 34.17 270 bottom
RE30  47K_0402_5%  [R_0402]  127.08 27.36 180 bottom
RE31  0_0402_5%  [R0402_0OHM]  120.83 11.66 90 bottom
RE32  10K_0402_5%  [R_0402]  113.72 11.66 90 bottom
RE33  0_0402_5%  [R0402_0OHM]  116.77 11.66 90 bottom
RE34  10K_0402_5%  [R_0402]  103.1 16.06 0 bottom
RE37  0_0402_5%  [R0402_0OHM]  126.63 25.53 180 bottom
RE38  10K_0402_5%  [R_0402]  103.1 16.95 0 bottom
RE39  0_0402_5%  [R_0402]  126.63 15.68 180 bottom
RE40  0_0402_5%  [R_0402]  126.63 14.66 180 bottom
RE43  0_0402_5%  [R_0402]  129.42 21.26 180 bottom
RE44  0_0402_5%  [R0402_0OHM]  125.25 26.47 0 bottom
RE45  100K_0402_5%  [R_0402]  128.5 20.38 0 bottom
RE46  4.7K_0402_5%  [R_0402]  126.63 13.64 180 bottom
RE47  4.7K_0402_5%  [R_0402]  125.25 32.69 0 bottom
RE49  100K_0402_5%  [R_0402]  171.38 117.83 90 bottom
RE50  10K_0402_5%  [R_0402]  12.45 66.73 180 bottom
RE58  100K_0402_5%  [R_0402]  128.5 15.42 0 bottom
RE59  0_0805_5%  [R_0805]  134.17 15.77 270 top
RE60  240_0402_1%  [R_0402]  91.24 52.84 270 top
RE61  0_0402_5%  [R0402_0OHM]  109.15 11.66 90 bottom
RE62  47K_0402_5%  [R_0402]  103.1 20.5 0 bottom
RE63  47K_0402_5%  [R_0402]  103.1 21.52 0 bottom
RE68  10K_0402_5%  [R_0402]  129.42 11.36 180 bottom
RE69  0_0402_5%  [R_0402]  111.94 33.25 90 bottom
RE70  10K_0402_5%  [R_0402]  110.93 33.25 90 bottom
RE71  10K_0402_5%  [R_0402]  126.63 22.53 180 bottom
RE80  0_0402_5%  [R0402_0OHM]  125.71 24.57 0 bottom
RE329  100K_0402_5%  [R_0402]  23.68 63.12 270 top
RE330  0_0603_5%  [R_0603]  10.34 70.48 270 top
RE331  0_0603_5%  [R_0603]  11.61 70.48 270 top
RE332  13.7K_0402_1%  [R_0402]  13.14 64.49 90 bottom
RE333  13.7K_0402_1%  [R_0402]  14.03 63.63 270 bottom
RE336  0_0402_5%  [R0402_0OHM]  25.71 63.12 270 top
RE337  0_0402_5%  [R0402_0OHM]  24.69 63.12 270 top
RE504  10K_0402_5%  [R_0402]  118.17 33.25 90 bottom
RH1  100K_0402_5%  [R_0402]  141.15 26.93 180 bottom
RH2  2K_0402_1%  [R_0402]  169.34 26.53 180 top
RH3  33_0402_5%  [R_0402]  142.07 27.79 0 bottom
RH4  20M_0402_5%  [R_0402]  141.33 11.49 0 bottom
RH5  590_0402_1%  [R_0402]  169.34 27.49 180 top
RH6  0_0402_5%  [R_0402]  139.38 11.43 270 bottom
RH7  2K_0402_1%  [R_0402]  165.65 12.51 270 top
RH10  0_0402_5%  [R0402_0OHM]  173.66 13.77 180 bottom
RH11  0_0402_5%  [R0402_0OHM]  173.66 14.66 180 bottom
RH12  0_0402_5%  [R0402_0OHM]  173.66 11.29 180 bottom
RH13  0_0402_5%  [R0402_0OHM]  173.66 12.18 180 bottom
RH14  22_0402_5%  [R_0402]  165.2 5.34 270 bottom
RH15  0_0402_5%  [R0402_0OHM]  173.66 9.45 180 bottom
RH16  0_0402_5%  [R0402_0OHM]  173.66 10.34 180 bottom
RH17  0_0402_5%  [R_0402]  176.26 10.47 0 bottom
RH18  0_0402_5%  [R0402_0OHM]  167.82 5.34 270 bottom
RH19  510_0402_5%  [R_0402]  145.73 3.69 270 top
RH20  22_0402_5%  [R_0402]  177.17 11.49 180 bottom
RH21  0_0402_5%  [R_0402]  168.84 3.66 90 bottom
RH22  510_0402_5%  [R_0402]  147.68 9.97 270 top
RH23  1M_0402_5%  [R_0402]  170.77 5.41 0 bottom
RH24  10M_0402_5%  [R_0402]  145.73 4.8 90 top
RH25  33_0402_5%  [R_0402]  142.99 29.76 180 bottom
RH26  8.2K_0402_5%  [R_0402]  140.23 30.27 0 bottom
RH27  0_0402_5%  [R0402_0OHM]  138.46 33.52 270 bottom
RH28  0_0402_5%  [R_0402]  139.41 32.6 90 bottom
RH29  33_0402_5%  [R_0402]  181.29 25.63 90 top
RH34  33_0402_5%  [R_0402]  183.57 21.72 270 top
RH35  33_0402_5%  [R_0402]  180.27 25.63 90 top
RH37  1K_0402_1%  [R_0402]  168.08 35.03 90 bottom
RH38  931_0402_1%  [R_0402]  166.3 28.43 90 top
RH39  10K_0402_5%  [R_0402]  161.98 31.12 270 top
RH40  10K_0402_5%  [R_0402]  144.89 11.87 0 top
RH41  10K_0402_5%  [R_0402]  159.89 35.88 270 bottom
RH51  0_0402_5%  [R_0402]  136.63 18.98 0 bottom
RH52  0_0402_5%  [R0402_0OHM]  136.63 17.96 0 bottom
RH53  10K_0402_5%  [R_0402]  139.48 21.07 0 bottom
RH54  11.8K_0402_1%  [R_0402]  151.49 5.27 270 bottom
RH56  0_0402_5%  [R_0402]  162.03 35.28 90 top
RH57  2.2K_0402_5%  [R_0402]  146.41 21.26 0 top
RH58  1K_0402_1%  [R_0402]  157.96 5.34 270 bottom
RH59  1K_0402_1%  [R_0402]  157.01 5.34 270 bottom
RH60  2.2K_0402_5%  [R_0402]  150.11 22.13 270 top
RH61  2.2K_0402_5%  [R_0402]  149.19 22.13 270 top
RH64  0_0402_5%  [R_0402]  145.55 24.31 180 top
RH65  0_0402_5%  [R_0402]  136.63 21.26 0 bottom
RH66  0_0402_5%  [R0402_0OHM]  146.69 14.41 180 top
RH67  0_0402_5%  [R_0402]  184.59 21.72 270 top
RH68  0_0402_5%  [R_0402]  162.03 29.33 0 top
RH69  0_0402_5%  [R_0402]  179.13 26.55 270 top
RH70  0_0402_5%  [R_0402]  139.4 22.15 0 bottom
